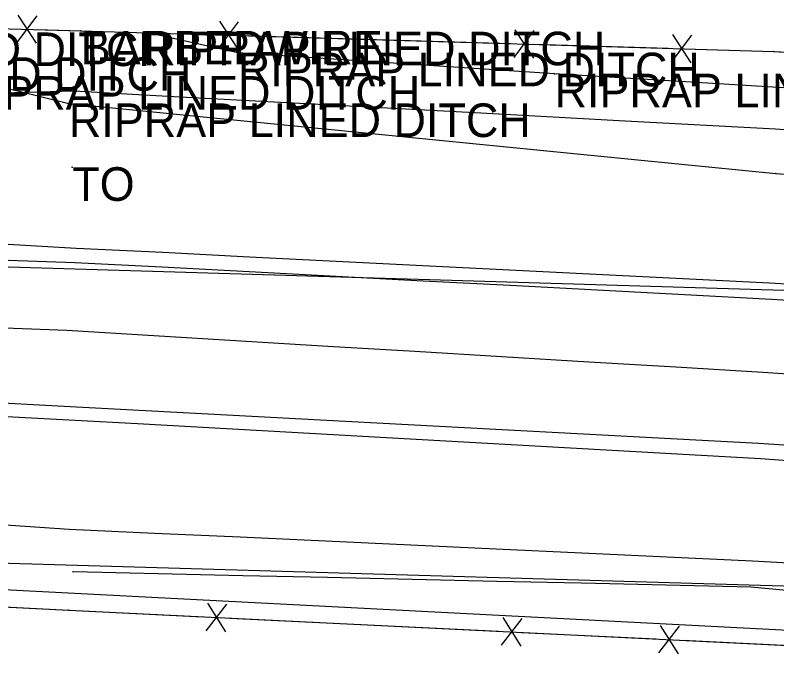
# Model space of a CAD drawing. Extents: x 675481 to 678499, y 212715 to 215285.
# Drawn here: x 676713.6 to 676826.9, y 214648.1 to 214746.2 of the extents above; entities that cross this region are included whole.
import ezdxf

# ---------------------------------------------------------------- set-up
doc = ezdxf.new("R2010")
doc.units = 0
for name, color, linetype in [('S_BASELINE', 7, 'Continuous'), ('S_DITCHLINE', 7, 'Continuous'), ('S_EDGE_PAVEMENT', 7, 'Continuous'), ('S_FENCE', 7, 'Continuous'), ('S_FENCE_ANNOT', 7, 'Continuous'), ('S_FIBER_OPTIC_CABLE', 7, 'Continuous'), ('S_GRD_PT_SYM', 7, 'Continuous'), ('S_MISC_TOPO_POINT', 7, 'Continuous'), ('S_MSC_PT_SYM', 7, 'Continuous'), ('S_PAVEMENT_CROWN', 7, 'Continuous'), ('S_SHOULDER', 7, 'Continuous'), ('S_STREAM', 7, 'Continuous')]:
    doc.layers.add(name, color=color, linetype=linetype)

msp = doc.modelspace()

# ---------------------------------------------------------------- linework, layer by layer
at = {"layer": 'S_BASELINE'}
msp.add_line((675887.93, 214733.6), (676879.32, 214703.75), dxfattribs=at)
at = {"layer": 'S_DITCHLINE'}
for points in [[(676684.59, 214672.17), (676686.62, 214672.03), (676704.15, 214670.89), (676721.67, 214669.74), (676734.37, 214669.15), (676747.08, 214668.56), (676759.79, 214667.97), (676772.49, 214667.38), (676785.2, 214666.79), (676797.91, 214666.21), (676810.61, 214665.62), (676823.32, 214665.03), (676844.67, 214663.84), (676866.02, 214662.65), (676887.37, 214661.46), (676908.72, 214660.27), (676914.74, 214658.57), (676915.33, 214654.64), (676902.17, 214653.74)], [(676722.14, 214663.43), (676722.3, 214663.41), (676734.9, 214663.13), (676747.49, 214662.85), (676760.09, 214662.57), (676772.68, 214662.28), (676785.28, 214662), (676797.87, 214661.72), (676810.47, 214661.44), (676823.06, 214661.15), (676842.84, 214659.3), (676862.62, 214657.45), (676882.39, 214655.6), (676902.17, 214653.74)]]:
    msp.add_lwpolyline(points, dxfattribs=at)
at = {"layer": 'S_EDGE_PAVEMENT'}
for points in [[(676677.25, 214711.01), (676699.88, 214710.21), (676722.5, 214709.42), (676735.45, 214708.74), (676748.41, 214708.05), (676761.36, 214707.37), (676774.32, 214706.69), (676787.27, 214706.01), (676800.23, 214705.33), (676813.18, 214704.64), (676826.14, 214703.96), (676838.77, 214703.19), (676851.4, 214702.42), (676864.03, 214701.65), (676876.65, 214700.88), (676889.28, 214700.1), (676901.91, 214699.33), (676914.54, 214698.56), (676927.17, 214697.79), (676942.37, 214697.01), (676957.56, 214696.24), (676972.76, 214695.46), (676987.95, 214694.68), (676999.79, 214693.96)], [(676676.07, 214690.47), (676698.02, 214689.27), (676719.97, 214688.08), (676733, 214687.38), (676746.03, 214686.69), (676759.06, 214685.99), (676772.1, 214685.3), (676785.13, 214684.61), (676798.16, 214683.91), (676811.19, 214683.22), (676824.22, 214682.52), (676837.04, 214681.68), (676849.87, 214680.84), (676862.69, 214680), (676875.51, 214679.16), (676888.34, 214678.31), (676901.16, 214677.47), (676913.98, 214676.63), (676926.8, 214675.79), (676941.84, 214675.17), (676956.87, 214674.55), (676971.9, 214673.93), (676986.94, 214673.32), (676998.53, 214672.68)]]:
    msp.add_lwpolyline(points, dxfattribs=at)
at = {"layer": 'S_FENCE'}
for p, q in [((676649.4, 214746.03), (676723.38, 214743.86)), ((676713.88, 214742.09), (676716.87, 214746.1)), ((676714, 214746.18), (676716.75, 214742.01)), ((676744, 214745.3), (676746.74, 214741.12)), ((676743.88, 214741.21), (676746.86, 214745.21)), ((676723.38, 214743.86), (676826.49, 214740.81)), ((676787.86, 214739.9), (676790.84, 214743.91)), ((676787.98, 214744), (676790.72, 214739.82)), ((676811.28, 214739.21), (676814.27, 214743.22)), ((676811.4, 214743.3), (676814.15, 214739.12)), ((676826.49, 214740.81), (676933.46, 214734.68)), ((676554.15, 214666.49), (676721.59, 214657.65)), ((676742.03, 214654.61), (676745.09, 214658.56)), ((676742.23, 214658.7), (676744.9, 214654.47)), ((676721.59, 214657.65), (676918.37, 214648.06)), ((676785.98, 214652.46), (676789.04, 214656.42)), ((676786.18, 214656.56), (676788.84, 214652.33)), ((676809.38, 214651.32), (676812.45, 214655.28)), ((676809.58, 214655.41), (676812.25, 214651.18))]:
    msp.add_line(p, q, dxfattribs=at)
for points in [[(676716.81, 214744.05), (676723.38, 214743.86)], [(676723.38, 214743.86), (676743.37, 214743.27)], [(676747.37, 214743.15), (676787.35, 214741.97)], [(676790.78, 214741.87), (676810.77, 214741.27)], [(676814.77, 214741.15), (676826.49, 214740.81)], [(676826.49, 214740.81), (676846.45, 214739.66)], [(676712.79, 214658.12), (676721.59, 214657.65)], [(676721.59, 214657.65), (676741.56, 214656.68)], [(676745.56, 214656.49), (676785.51, 214654.54)], [(676788.94, 214654.37), (676808.92, 214653.4)], [(676812.91, 214653.2), (676852.86, 214651.25)]]:
    msp.add_lwpolyline(points, dxfattribs=at)
at = {"layer": 'S_FIBER_OPTIC_CABLE'}
for p, q in [((676695.14, 214665.17), (676903.62, 214659.05)), ((676694.38, 214661.65), (676902.67, 214650.86))]:
    msp.add_line(p, q, dxfattribs=at)
at = {"layer": 'S_GRD_PT_SYM'}
for points in [[(676732.69, 214743.73), (676732.69, 214743.77), (676732.69, 214743.73), (676732.64, 214743.73), (676732.69, 214743.73), (676732.69, 214743.68), (676732.69, 214743.73), (676732.74, 214743.73)], [(676746.75, 214740.61), (676746.75, 214740.66), (676746.75, 214740.61), (676746.7, 214740.61), (676746.75, 214740.61), (676746.75, 214740.56), (676746.75, 214740.61), (676746.8, 214740.61)], [(676793.87, 214737.48), (676793.87, 214737.52), (676793.87, 214737.48), (676793.82, 214737.48), (676793.87, 214737.48), (676793.87, 214737.43), (676793.87, 214737.48), (676793.92, 214737.48)], [(676721.61, 214733.06), (676721.61, 214733.11), (676721.61, 214733.06), (676721.56, 214733.06), (676721.61, 214733.06), (676721.61, 214733.01), (676721.61, 214733.06), (676721.66, 214733.06)], [(676722.11, 214723.57), (676722.11, 214723.62), (676722.11, 214723.57), (676722.06, 214723.57), (676722.11, 214723.57), (676722.11, 214723.52), (676722.11, 214723.57), (676722.16, 214723.57)], [(676826.77, 214722.64), (676826.77, 214722.69), (676826.77, 214722.64), (676826.72, 214722.64), (676826.77, 214722.64), (676826.77, 214722.59), (676826.77, 214722.64), (676826.82, 214722.64)]]:
    msp.add_lwpolyline(points, dxfattribs=at)
at = {"layer": 'S_MISC_TOPO_POINT'}
for p, q in [((676746.75, 214740.61), (676732.69, 214743.73)), ((676793.87, 214737.48), (676746.75, 214740.61)), ((676842.24, 214734.53), (676793.87, 214737.48)), ((676705.16, 214737.13), (676721.61, 214733.06)), ((676721.61, 214733.06), (676826.77, 214722.64)), ((676826.77, 214722.64), (676934.78, 214714.6))]:
    msp.add_line(p, q, dxfattribs=at)
at = {"layer": 'S_MSC_PT_SYM'}
for points in [[(676723.38, 214743.86), (676723.38, 214743.91), (676723.38, 214743.86), (676723.33, 214743.86), (676723.38, 214743.86), (676723.38, 214743.81), (676723.38, 214743.86), (676723.43, 214743.86)], [(676826.49, 214740.81), (676826.49, 214740.86), (676826.49, 214740.81), (676826.44, 214740.81), (676826.49, 214740.81), (676826.49, 214740.76), (676826.49, 214740.81), (676826.54, 214740.81)], [(676721.59, 214657.65), (676721.59, 214657.7), (676721.59, 214657.65), (676721.54, 214657.65), (676721.59, 214657.65), (676721.59, 214657.6), (676721.59, 214657.65), (676721.64, 214657.65)]]:
    msp.add_lwpolyline(points, dxfattribs=at)
at = {"layer": 'S_PAVEMENT_CROWN'}
msp.add_lwpolyline([(676676.38, 214701.07), (676698.84, 214700.19), (676721.29, 214699.32), (676734.24, 214698.53), (676747.19, 214697.75), (676760.13, 214696.97), (676773.08, 214696.19), (676786.03, 214695.41), (676798.98, 214694.63), (676811.92, 214693.85), (676824.87, 214693.07), (676837.62, 214692.22), (676850.38, 214691.37), (676863.13, 214690.52), (676875.89, 214689.66), (676888.65, 214688.81), (676901.4, 214687.96), (676914.16, 214687.11), (676926.91, 214686.26), (676939.91, 214685.55), (676952.91, 214684.85), (676965.91, 214684.15), (676978.91, 214683.45), (676999.41, 214683.17)], dxfattribs=at)
at = {"layer": 'S_SHOULDER'}
for points in [[(676678.76, 214714.1), (676700.72, 214712.83), (676722.69, 214711.55), (676735.58, 214710.91), (676748.48, 214710.26), (676761.37, 214709.61), (676774.27, 214708.96), (676787.16, 214708.31), (676800.06, 214707.66), (676812.95, 214707.01), (676825.85, 214706.36), (676838.52, 214705.61), (676851.19, 214704.86), (676863.86, 214704.11), (676876.53, 214703.36), (676889.2, 214702.61), (676901.88, 214701.86), (676914.55, 214701.12), (676927.22, 214700.37), (676946.23, 214699.69), (676965.23, 214699.02), (676981.46, 214697.75), (676997.69, 214696.47)], [(676676.21, 214688.53), (676694.75, 214687.49), (676713.28, 214686.45), (676731.82, 214685.42), (676750.35, 214684.38), (676768.89, 214683.35), (676787.42, 214682.31), (676805.96, 214681.28), (676824.49, 214680.24), (676846.91, 214678.62), (676869.33, 214676.99), (676891.75, 214675.37), (676914.16, 214673.75)]]:
    msp.add_lwpolyline(points, dxfattribs=at)
at = {"layer": 'S_STREAM'}
msp.add_lwpolyline([(676704.61, 214734.46), (676722.37, 214734.95), (676737.25, 214734.11), (676759.62, 214732.9), (676781.99, 214731.69), (676804.37, 214730.48), (676826.74, 214729.27), (676840.32, 214728.33)], dxfattribs=at)

# ---------------------------------------------------------------- texts
at = {"layer": 'S_FENCE_ANNOT'}
msp.add_text('BARBEDWIRE', height=5, dxfattribs=at).set_placement((676723.38, 214738.86))
at = {"layer": 'S_MISC_TOPO_POINT'}
for s, p in [('RIPRAP LINED DITCH', (676668.05, 214738.62)), ('RIPRAP LINED DITCH', (676732.69, 214738.73)), ('RIPRAP LINED DITCH', (676671.11, 214734.94)), ('RIPRAP LINED DITCH', (676746.75, 214735.61)), ('RIPRAP LINED DITCH', (676793.87, 214732.48)), ('RIPRAP LINED DITCH', (676705.16, 214732.13)), ('RIPRAP LINED DITCH', (676721.61, 214728.06)), ('TO', (676722.11, 214718.57))]:
    msp.add_text(s, height=5, dxfattribs=at).set_placement(p)

doc.saveas('drawing.dxf')
